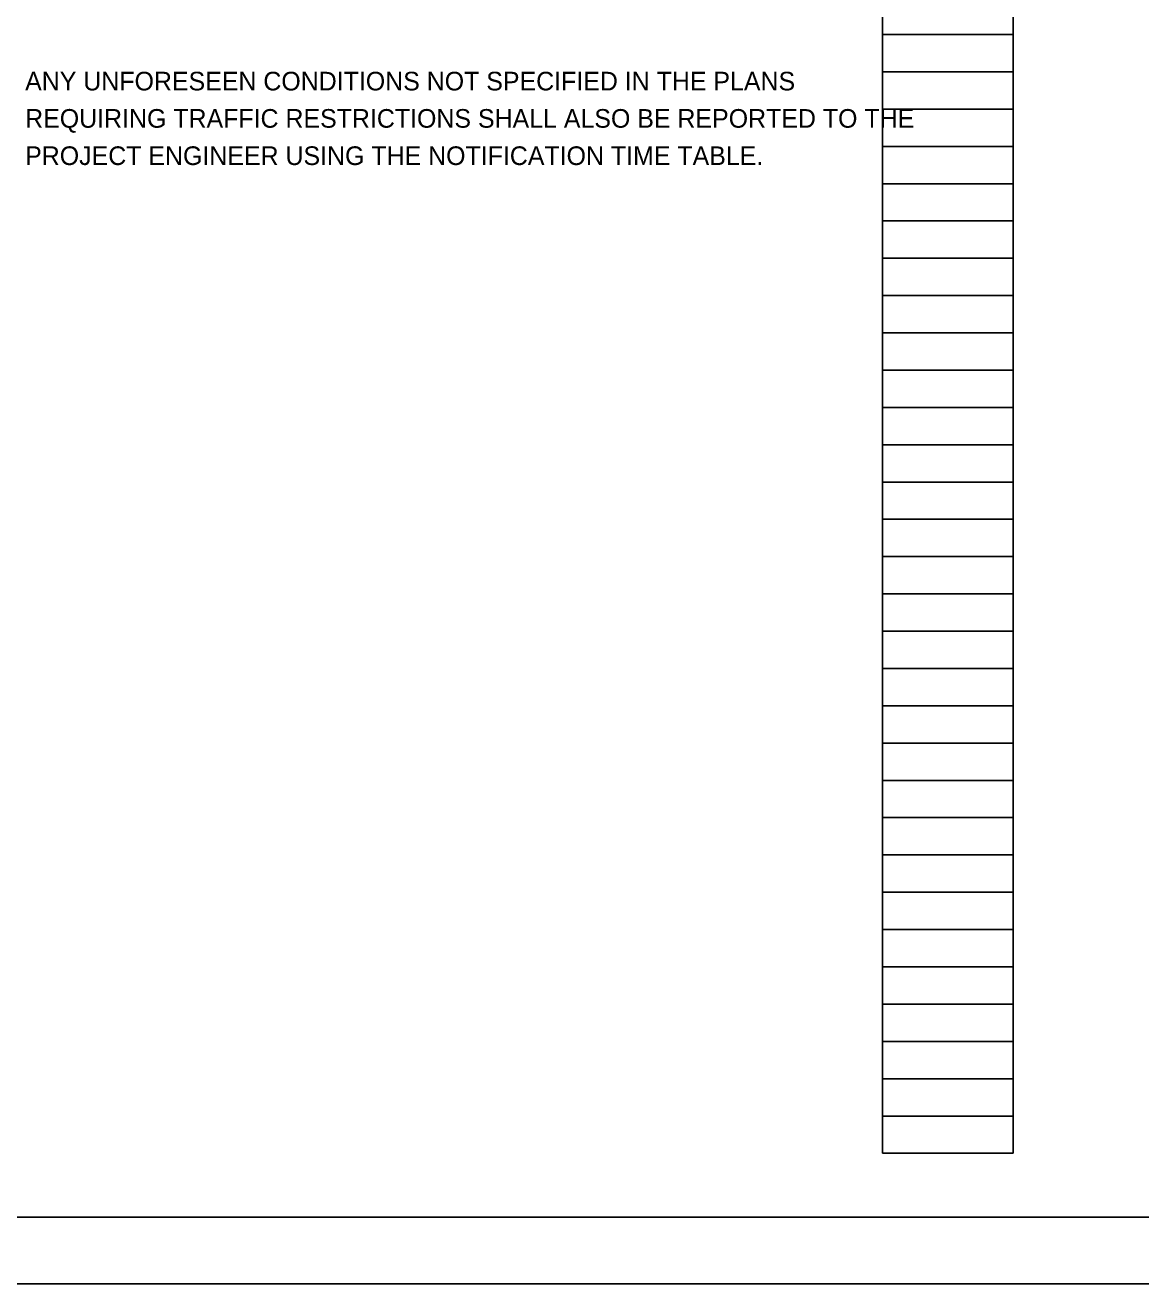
# Model space of a CAD drawing. Extents: x 0 to 52.3, y 0 to 22.
# Drawn here: x 17.24 to 25.62, y 0 to 9.45 of the extents above; entities that cross this region are included whole.
import ezdxf

# ---------------------------------------------------------------- set-up
doc = ezdxf.new("R2010")
doc.units = 0
for name, color, linetype in [('SH_Border', 7, 'Continuous'), ('SH_Cut_Line', 7, 'Continuous'), ('SH_Data', 7, 'Continuous'), ('SH_Text', 7, 'Continuous')]:
    doc.layers.add(name, color=color, linetype=linetype)

msp = doc.modelspace()

# ---------------------------------------------------------------- linework, layer by layer
at = {"layer": 'SH_Border'}
msp.add_lwpolyline([(1.5, 21.5), (33.5, 21.5), (33.5, 0.5), (1.5, 0.5)], close=True, dxfattribs=at)
at = {"layer": 'SH_Cut_Line'}
msp.add_lwpolyline([(0, 0), (34, 0), (34, 22), (0, 22)], close=True, dxfattribs=at)
at = {"layer": 'SH_Data'}
for p, q in [((23.68, 0.98), (23.68, 21.14)), ((24.66, 0.98), (24.66, 21.14)), ((23.68, 9.38), (24.66, 9.38)), ((23.68, 9.1), (24.66, 9.1)), ((23.68, 8.82), (24.66, 8.82)), ((23.68, 8.54), (24.66, 8.54)), ((23.68, 8.26), (24.66, 8.26)), ((23.68, 7.98), (24.66, 7.98)), ((23.68, 7.7), (24.66, 7.7)), ((23.68, 7.42), (24.66, 7.42)), ((23.68, 7.14), (24.66, 7.14)), ((23.68, 6.86), (24.66, 6.86)), ((23.68, 6.58), (24.66, 6.58)), ((23.68, 6.3), (24.66, 6.3)), ((23.68, 6.02), (24.66, 6.02)), ((23.68, 5.74), (24.66, 5.74)), ((23.68, 5.46), (24.66, 5.46)), ((23.68, 5.18), (24.66, 5.18)), ((23.68, 4.9), (24.66, 4.9)), ((23.68, 4.62), (24.66, 4.62)), ((23.68, 4.34), (24.66, 4.34)), ((23.68, 4.06), (24.66, 4.06)), ((23.68, 3.78), (24.66, 3.78)), ((23.68, 3.5), (24.66, 3.5)), ((23.68, 3.22), (24.66, 3.22)), ((23.68, 2.94), (24.66, 2.94)), ((23.68, 2.66), (24.66, 2.66)), ((23.68, 2.38), (24.66, 2.38)), ((23.68, 2.1), (24.66, 2.1)), ((23.68, 1.82), (24.66, 1.82)), ((23.68, 1.54), (24.66, 1.54)), ((23.68, 1.26), (24.66, 1.26)), ((23.68, 0.98), (24.66, 0.98))]:
    msp.add_line(p, q, dxfattribs=at)

# ---------------------------------------------------------------- texts
at = {"layer": 'SH_Text'}
for s, p in [('ANY UNFORESEEN CONDITIONS NOT SPECIFIED IN THE PLANS ', (17.24, 8.96)), ('REQUIRING TRAFFIC RESTRICTIONS SHALL ALSO BE REPORTED TO THE ', (17.24, 8.68)), ('PROJECT ENGINEER USING THE NOTIFICATION TIME TABLE.', (17.24, 8.4))]:
    msp.add_text(s, height=0.14, dxfattribs=at).set_placement(p)

doc.saveas('drawing.dxf')
